(* Logix 5000 project; controller Hardy_1769_Sample_Program vendor 1 type 14 code 151 rev 30.11; software revision 30.02; part 4 of 5 *)
(* tags used below, declared in another part *)
   Control_Bits : BOOL[32];   // Control Bits For All Routines In This Program
   Control_Bits1 : BOOL[32];
   Current_Metric : INT;   // Current Metric Settings
   Default_Return_Flt : HardyFloatWeight;   // Default Return Values With Weight In Foating Point Format
   Default_Return_Int : HardyIntWeight;   // Default Return Values With Weight In Integer Format
   Error_Flag : BOOL;
   Metric : INT;   // New Metric Setting
   Motion : BOOL;
   One_Shot : BOOL[32];   // One Shots For Program Control
   Read_Float_Parameters_0 : HardyFloatParam0;   // Read Parameter 0 Values From Module Using Float Values
   Read_Float_Parameters_1 : HardyFloatParam1;   // Read Parameter 1 Values From Module Using Float Values
   Read_Int_Parameters_0 : HardyIntParam0;   // Read Parameter 0 Values From Module Using Int Values
   Read_Int_Parameters_1 : HardyIntParam1;   // Read Parameter 1 Values From Module Using Int Values
   Sensor_Select : INT;   // Load Cell Selected For Reading Serial Number
   Serial_Number : HardyC2SerialNumber;   // Serial Number of Selected Load Cell Analog With Sensitivity and Capacity
   Signal_Select : INT;   // Signal To Select For Stability Test
   Stability_Float : HardyFloatWeight;   // Results Of Stability Test Float Format
   Stability_Int : HardyIntWeight;   // Results Of Stability Test Int Format
   Status_Return : HardyCmdResult;   // Command Status Returned
   Write_Float_Param_0 : HardyFloatParam0;   // New Parameter 0 Values In Float Format
   Write_Float_Param_1 : HardyFloatParam1;   // New Parameter 1 Values In Float Format
   Write_Int_Param_0 : HardyIntParam0;   // New Parameter 0 Value Int Format
   Write_Int_Param_1 : HardyIntParam1;   // New Parameter 1 Value Int Format
(* Hardy_HI1769_Scale_1, continued *)

ROUTINE Read_Parameters_0   (* ladder *)
// READ PARAMETER 0 VALUES
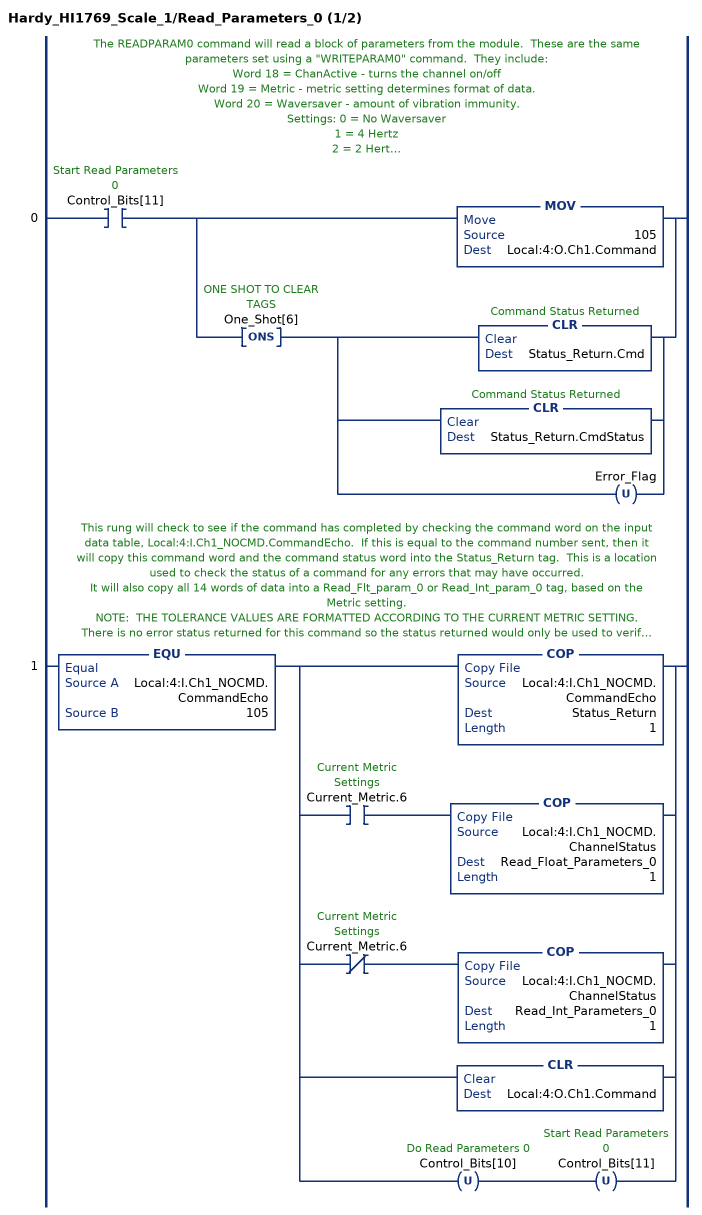
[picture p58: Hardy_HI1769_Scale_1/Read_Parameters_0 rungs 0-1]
   // The READPARAM0 command will read a block of parameters from the module.  These are the same parameters set using a "WRITEPARAM0" command.  They include:
   // Word 18 = ChanActive - turns the channel on/off
   // Word 19 = Metric - metric setting determines format of data.
   // Word 20 = Waversaver - amount of vibration immunity.
   //     Settings: 0 = No Waversaver
   //               1 = 4 Hertz
   //               2 = 2 Hertz
   //               3 = 1 Hertz
   //               4 = 0.5 Hertz
   //               5 = 0.25 Hertz
   // Word 21 = NumAverages - number of readings averaged together
   // Word 22 = ZeroTrackEnable - AutoZero tracking on/off
   // Word 23 = ROC Time Base
   // Word 24 = AutoZeroTolerance, LSW - Auto Zero Tracking tolerance
   // Word 25 = AutoZeroTolerance, MSW - Auto Zero Tracking tolerance
   // Word 26 = Motion Tolerance LSW - used to determine motion
   // Word 27 = Motion Tolerance MSW - used to determine motion
   // Word 28 = Zero Tolerance LSW - tolerance for zero command
   // Word 29 = Zero Tolerance MSW - tolerance for zero command
   // Word 30 = unused
   // Word 31 = unused
   // This rung will initiate the READPARAM0 command by writing the command number, #105, to the output table, LOCAL:4:O.CH1.Command.
   // Here the program will also clear the Status_Return tag and ERROR_FLAG of any previous values before running this command and receiving its return values.
   0: XIC(Control_Bits[11])[MOV(105,Local:4:O.Ch1.Command) ,ONS(One_Shot[6]) [CLR(Status_Return.Cmd) ,CLR(Status_Return.CmdStatus) ,OTU(Error_Flag) ] ];
   // This rung will check to see if the command has completed by checking the command word on the input data table, Local:4:I.Ch1_NOCMD.CommandEcho.  If this is equal to the command number sent, then it will copy this command word and the command status word into the Status_Return tag.  This is a location used to check the status of a command for any errors that may have occurred.
   // It will also copy all 14 words of data into a Read_Flt_param_0 or Read_Int_param_0 tag, based on the Metric setting.
   // NOTE:  THE TOLERANCE VALUES ARE FORMATTED ACCORDING TO THE CURRENT METRIC SETTING.
   // There is no error status returned for this command so the status returned would only be used to verify what command was run last.
   // Finally, the command is cleared from the output table,  Local:4:O.Ch1_NOCMD.Command, and any control bits are cleared.
   1: EQU(Local:4:I.Ch1_NOCMD.CommandEcho,105)[COP(Local:4:I.Ch1_NOCMD.CommandEcho,Status_Return,1) ,XIC(Current_Metric.6) COP(Local:4:I.Ch1_NOCMD.ChannelStatus,Read_Float_Parameters_0,1) ,XIO(Current_Metric.6) COP(Local:4:I.Ch1_NOCMD.ChannelStatus,Read_Int_Parameters_0,1) ,CLR(Local:4:O.Ch1.Command) ,OTU(Control_Bits[10]) OTU(Control_Bits[11]) ];
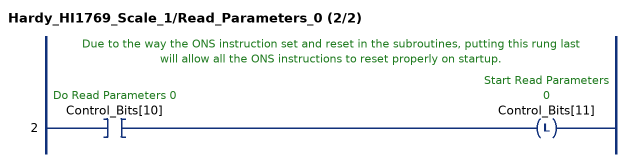
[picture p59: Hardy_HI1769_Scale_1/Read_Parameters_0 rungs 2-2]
   // Due to the way the ONS instruction set and reset in the subroutines, putting this rung last will allow all the ONS instructions to reset properly on startup.
   2: XIC(Control_Bits[10])OTL(Control_Bits[11]);
END_ROUTINE

ROUTINE Read_Parameters_1   (* ladder *)
// READ PARAMETER 1 VALUES
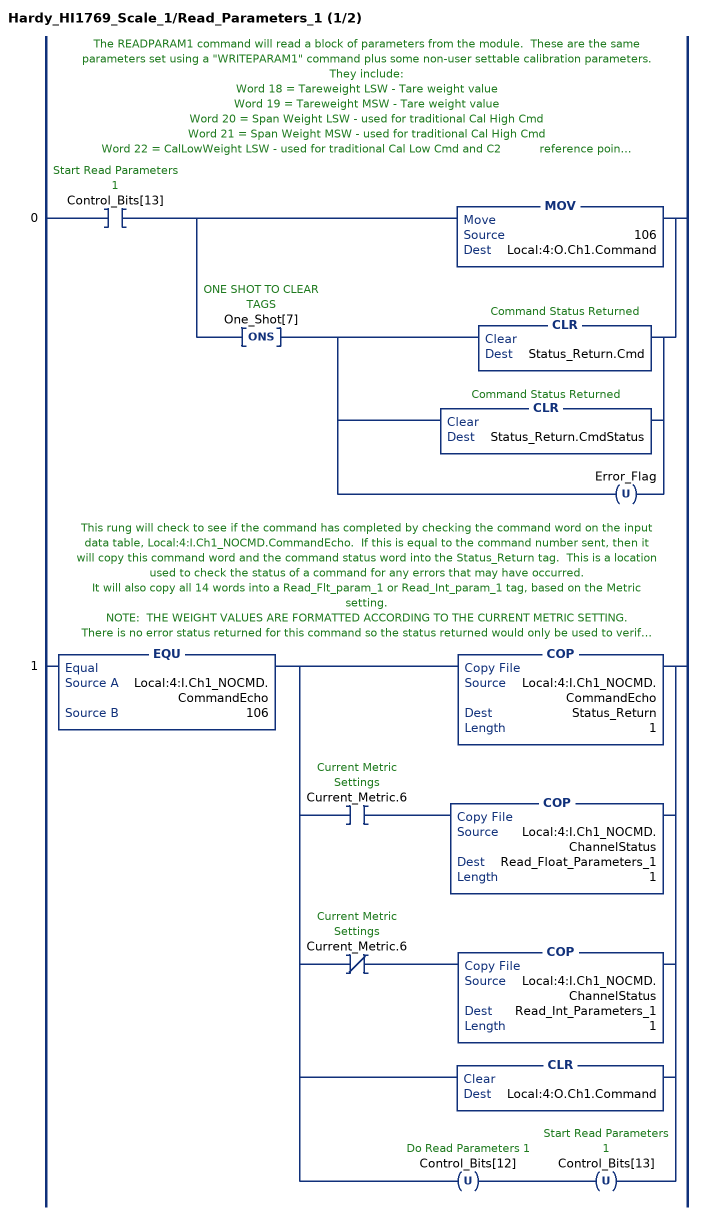
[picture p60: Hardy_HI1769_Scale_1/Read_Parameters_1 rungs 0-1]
   // The READPARAM1 command will read a block of parameters from the module.  These are the same parameters set using a "WRITEPARAM1" command plus some non-user settable calibration parameters.  They include:
   // Word 18 = Tareweight LSW - Tare weight value
   // Word 19 = Tareweight MSW - Tare weight value
   // Word 20 = Span Weight LSW - used for traditional Cal High Cmd
   // Word 21 = Span Weight MSW - used for traditional Cal High Cmd
   // Word 22 = CalLowWeight LSW - used for traditional Cal Low Cmd and C2           reference point
   // Word 23 = CalLowWeight MSW - used for traditional Cal Low Cmd and C2           reference point
   // Word 24 = Zerocount LSW - A/D counts at last ZEROCMD (read only)
   // Word 25 = Zerocount MSW - A/D counts at last ZEROCMD (read only)
   // Word 26 = Calzerocount LSW - A/D counts at zero weight obtained at the last calibration (read only)
   // Word 27 = Calzerocount MSW - A/D counts at zero weight obtained at the last calibration (read only)
   // Word 28 = CalLowCount LSW - A/D counts at CalLowWeight (read only)
   // Word 29 = CalLowCount MSW - A/D counts at CalLowWeight (read only)
   // Word 30 = CalHighCount LSW - A/D counts at span weight (traditional cal only) (read only)
   // Word 31 = CalHighCount MSW - A/D counts at span weight (traditional cal only) (read only)
   // This rung will initiate the READPARAM1 command by writing the command number, #106, to the output table, Local:4:O.Ch1.Command.
   // Here the program will also clear the Status_Return tag and ERROR_FLAG of any previous values before running this command and receiving its return values.
   0: XIC(Control_Bits[13])[MOV(106,Local:4:O.Ch1.Command) ,ONS(One_Shot[7]) [CLR(Status_Return.Cmd) ,CLR(Status_Return.CmdStatus) ,OTU(Error_Flag) ] ];
   // This rung will check to see if the command has completed by checking the command word on the input data table, Local:4:I.Ch1_NOCMD.CommandEcho.  If this is equal to the command number sent, then it will copy this command word and the command status word into the Status_Return tag.  This is a location used to check the status of a command for any errors that may have occurred.
   // It will also copy all 14 words into a Read_Flt_param_1 or Read_Int_param_1 tag, based on the Metric setting.
   // NOTE:  THE WEIGHT VALUES ARE FORMATTED ACCORDING TO THE CURRENT METRIC SETTING.
   // There is no error status returned for this command so the status returned would only be used to verify what command was run last.
   // Finally, the command is cleared from the output table, Local:4:O.Ch1.Command, and any control bits are cleared.
   1: EQU(Local:4:I.Ch1_NOCMD.CommandEcho,106)[COP(Local:4:I.Ch1_NOCMD.CommandEcho,Status_Return,1) ,XIC(Current_Metric.6) COP(Local:4:I.Ch1_NOCMD.ChannelStatus,Read_Float_Parameters_1,1) ,XIO(Current_Metric.6) COP(Local:4:I.Ch1_NOCMD.ChannelStatus,Read_Int_Parameters_1,1) ,CLR(Local:4:O.Ch1.Command) ,OTU(Control_Bits[12]) OTU(Control_Bits[13]) ];
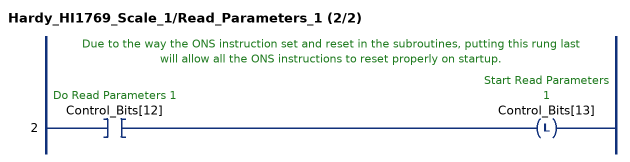
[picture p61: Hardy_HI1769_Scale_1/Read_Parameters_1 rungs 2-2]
   // Due to the way the ONS instruction set and reset in the subroutines, putting this rung last will allow all the ONS instructions to reset properly on startup.
   2: XIC(Control_Bits[12])OTL(Control_Bits[13]);
END_ROUTINE

ROUTINE Read_Serial_Numbers   (* ladder *)
// READS SERIAL NUMBER FROM C2 LOAD CELLS
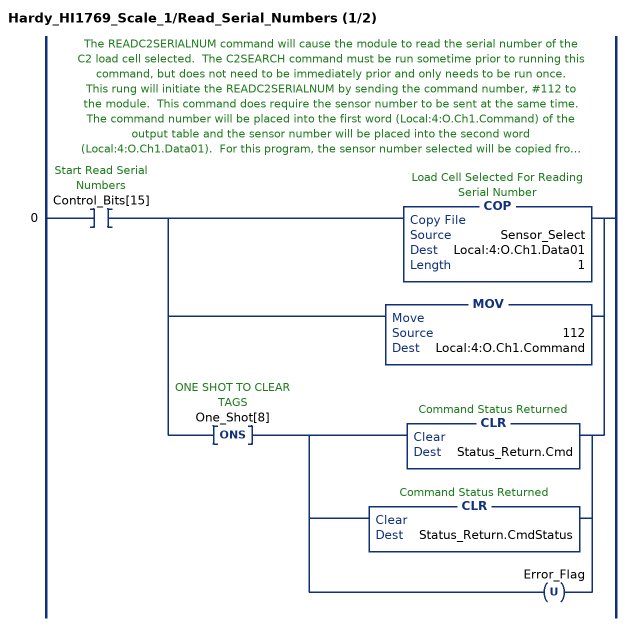
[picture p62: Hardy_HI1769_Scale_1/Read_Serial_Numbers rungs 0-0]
   // The READC2SERIALNUM command will cause the module to read the serial number of the C2 load cell selected.  The C2SEARCH command must be run sometime prior to running this command, but does not need to be immediately prior and only needs to be run once.
   // This rung will initiate the READC2SERIALNUM by sending the command number, #112 to the module.  This command does require the sensor number to be sent at the same time.  The command number will be placed into the first word (Local:4:O.Ch1.Command) of the output table and the sensor number will be placed into the second word (Local:4:O.Ch1.Data01).  For this program, the sensor number selected will be copied from data tag sensor_sel.
   // The data read from the READC2SERIALNUM command contains:
   // word 18 - word 25 = serial number read as ASCII characters
   // word 26 = sensitivity LSW - mv/v rating of load cell
   // word 27 = sensitivity MSW - mv/v rating of load cell
   // word 28 = capacity LSW = capacity of load cell
   // word 29 = capacity MSW = capacity of load cell
   // word 30 = unused
   // word 31 = unused
   // NOTE:  SENSITIVITY IS AN ITEGER WITH 4 DECIMAL PLACES AND CAPACITY IS AN INTEGER WITH ZERO DECIMAL PLACES AND UNITS OF POUNDS.
   // Here the program will also clear the Status_Return tag and ERROR_FLAG of any previous values before running this command and receiving its return values.
   0: XIC(Control_Bits[15])[COP(Sensor_Select,Local:4:O.Ch1.Data01,1) ,MOV(112,Local:4:O.Ch1.Command) ,ONS(One_Shot[8]) [CLR(Status_Return.Cmd) ,CLR(Status_Return.CmdStatus) ,OTU(Error_Flag) ] ];
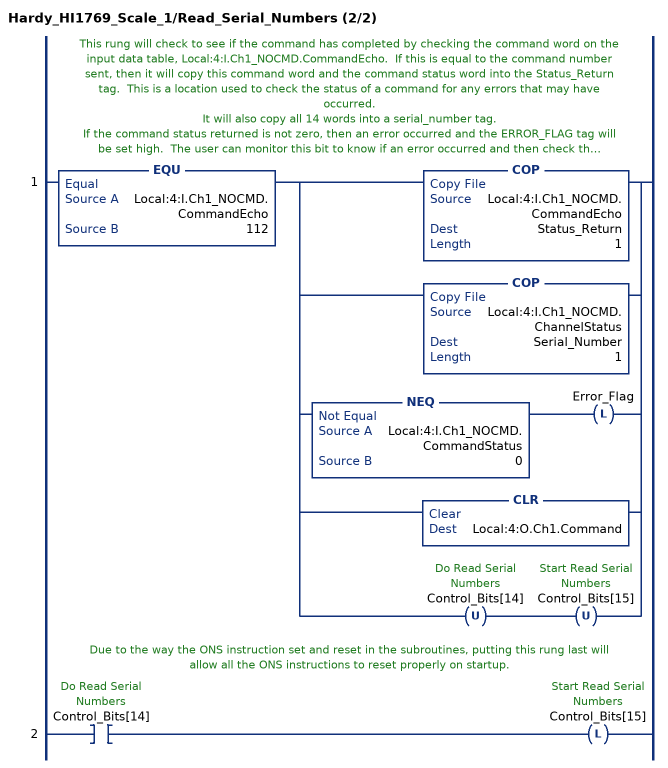
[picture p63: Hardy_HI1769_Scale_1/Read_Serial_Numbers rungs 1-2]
   // This rung will check to see if the command has completed by checking the command word on the input data table, Local:4:I.Ch1_NOCMD.CommandEcho.  If this is equal to the command number sent, then it will copy this command word and the command status word into the Status_Return tag.  This is a location used to check the status of a command for any errors that may have occurred.
   // It will also copy all 14 words into a serial_number tag.
   // If the command status returned is not zero, then an error occurred and the ERROR_FLAG tag will be set high.  The user can monitor this bit to know if an error occurred and then check the Status_Return tag for the command and status return.
   // Finally, the command is cleared from the output table, Local:4:O.Ch1.Command, and any control bits are cleared.
   1: EQU(Local:4:I.Ch1_NOCMD.CommandEcho,112)[COP(Local:4:I.Ch1_NOCMD.CommandEcho,Status_Return,1) ,COP(Local:4:I.Ch1_NOCMD.ChannelStatus,Serial_Number,1) ,NEQ(Local:4:I.Ch1_NOCMD.CommandStatus,0) OTL(Error_Flag) ,CLR(Local:4:O.Ch1.Command) ,OTU(Control_Bits[14]) OTU(Control_Bits[15]) ];
   // Due to the way the ONS instruction set and reset in the subroutines, putting this rung last will allow all the ONS instructions to reset properly on startup.
   2: XIC(Control_Bits[14])OTL(Control_Bits[15]);
END_ROUTINE

ROUTINE Reload_Non_Volatile   (* ladder *)
// RESTORE SETTINGS FROM NON-VOLATILE MEMORY
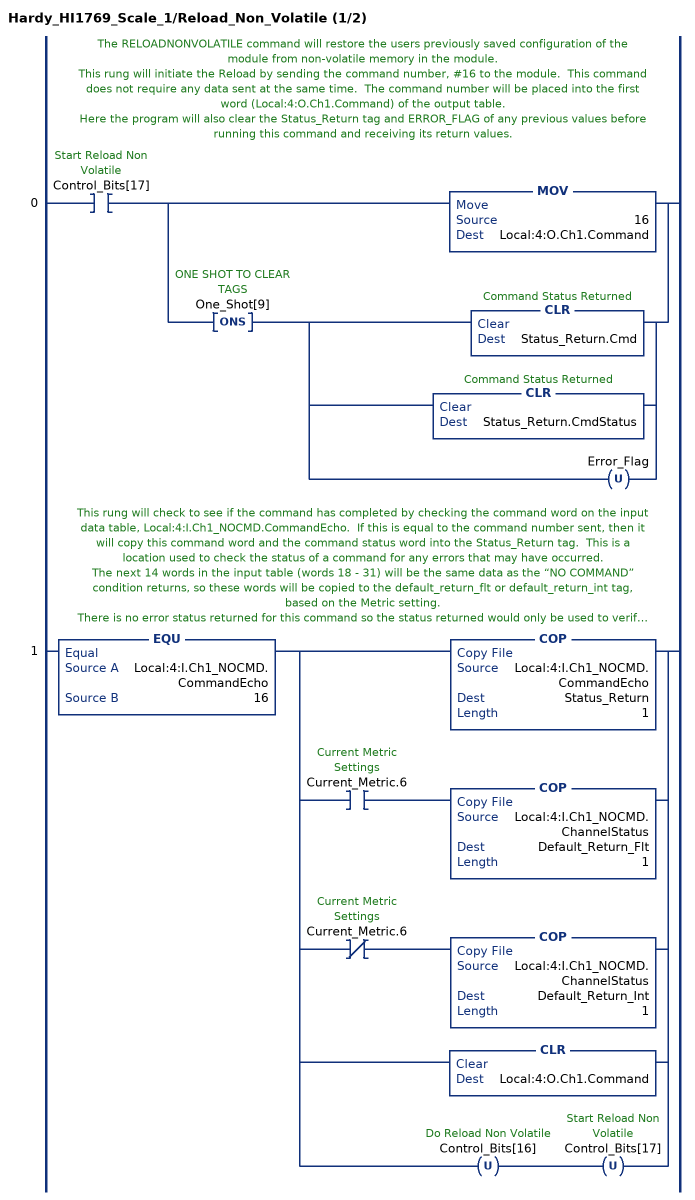
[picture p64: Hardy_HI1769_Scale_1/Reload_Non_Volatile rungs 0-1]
   // The RELOADNONVOLATILE command will restore the users previously saved configuration of the module from non-volatile memory in the module.
   // This rung will initiate the Reload by sending the command number, #16 to the module.  This command does not require any data sent at the same time.  The command number will be placed into the first word (Local:4:O.Ch1.Command) of the output table.
   // Here the program will also clear the Status_Return tag and ERROR_FLAG of any previous values before running this command and receiving its return values.
   0: XIC(Control_Bits[17])[MOV(16,Local:4:O.Ch1.Command) ,ONS(One_Shot[9]) [CLR(Status_Return.Cmd) ,CLR(Status_Return.CmdStatus) ,OTU(Error_Flag) ] ];
   // This rung will check to see if the command has completed by checking the command word on the input data table, Local:4:I.Ch1_NOCMD.CommandEcho.  If this is equal to the command number sent, then it will copy this command word and the command status word into the Status_Return tag.  This is a location used to check the status of a command for any errors that may have occurred.
   // The next 14 words in the input table (words 18 - 31) will be the same data as the “NO COMMAND” condition returns, so these words will be copied to the default_return_flt or default_return_int tag, based on the Metric setting.
   // There is no error status returned for this command so the status returned would only be used to verify what command was run last.
   // Finally, the command is cleared from the output table, Local:4:O.Ch1.Command, and any control bits are cleared.
   1: EQU(Local:4:I.Ch1_NOCMD.CommandEcho,16)[COP(Local:4:I.Ch1_NOCMD.CommandEcho,Status_Return,1) ,XIC(Current_Metric.6) COP(Local:4:I.Ch1_NOCMD.ChannelStatus,Default_Return_Flt,1) ,XIO(Current_Metric.6) COP(Local:4:I.Ch1_NOCMD.ChannelStatus,Default_Return_Int,1) ,CLR(Local:4:O.Ch1.Command) ,OTU(Control_Bits[16]) OTU(Control_Bits[17]) ];
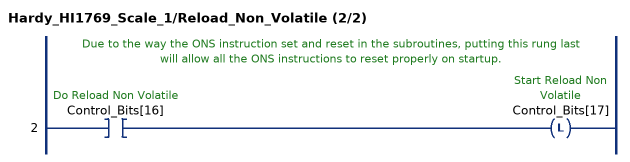
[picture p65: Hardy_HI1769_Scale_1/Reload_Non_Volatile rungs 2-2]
   // Due to the way the ONS instruction set and reset in the subroutines, putting this rung last will allow all the ONS instructions to reset properly on startup.
   2: XIC(Control_Bits[16])OTL(Control_Bits[17]);
END_ROUTINE

ROUTINE Stability_Test   (* ladder *)
// ALLOWS CHECK OF STABILITY OF SYSTEM
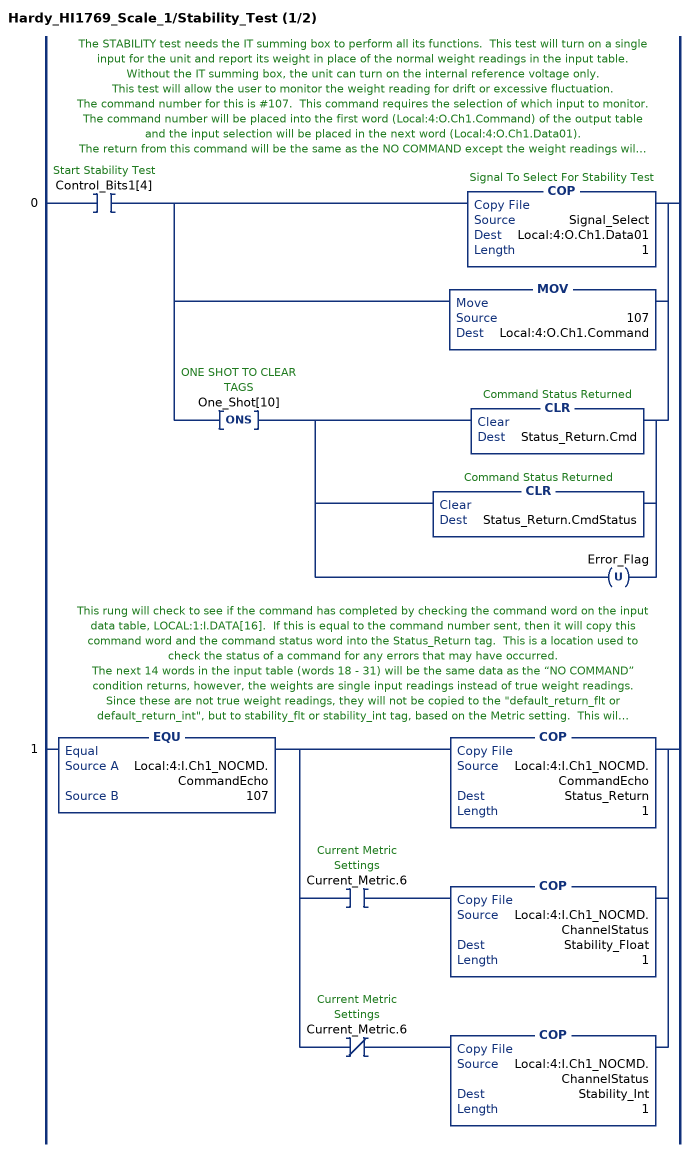
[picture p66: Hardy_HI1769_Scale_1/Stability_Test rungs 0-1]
   // The STABILITY test needs the IT summing box to perform all its functions.  This test will turn on a single input for the unit and report its weight in place of the normal weight readings in the input table.  Without the IT summing box, the unit can turn on the internal reference voltage only.
   // This test will allow the user to monitor the weight reading for drift or excessive fluctuation.
   // The command number for this is #107.  This command requires the selection of which input to monitor.  The command number will be placed into the first word (Local:4:O.Ch1.Command) of the output table and the input selection will be placed in the next word (Local:4:O.Ch1.Data01).
   // The return from this command will be the same as the NO COMMAND except the weight readings will reflect the reading based only on the input selected.  The selections are:
   // 0 = Internal reference voltage - checks if the input circuits are stable
   // 1-4 = load cell selection - checks if selected l/c is stable
   // 5 = reference voltage from IT JBOX - checks if cable is causing noise
   // All weight values will then be affected by this selection during the time the command number is left unchanged in the output table.
   // This rung will copy the selection into the output table at Local:4:O.Ch1.Data01 (from signal_select), and the command number for the STABILITY test, command #107, into word Local:4:O.Ch1.Command.  The user must have the selection value entered into the signal_select tag prior to running this routine, otherwise an error could occur.
   // Here the program will also clear the Status_Return tag and ERROR_FLAG of any previous values before running this command and receiving its return values.
   0: XIC(Control_Bits1[4])[COP(Signal_Select,Local:4:O.Ch1.Data01,1) ,MOV(107,Local:4:O.Ch1.Command) ,ONS(One_Shot[10]) [CLR(Status_Return.Cmd) ,CLR(Status_Return.CmdStatus) ,OTU(Error_Flag) ] ];
   // This rung will check to see if the command has completed by checking the command word on the input data table, LOCAL:1:I.DATA[16].  If this is equal to the command number sent, then it will copy this command word and the command status word into the Status_Return tag.  This is a location used to check the status of a command for any errors that may have occurred.
   // The next 14 words in the input table (words 18 - 31) will be the same data as the “NO COMMAND” condition returns, however, the weights are single input readings instead of true weight readings.  Since these are not true weight readings, they will not be copied to the "default_return_flt or default_return_int", but to stability_flt or stability_int tag, based on the Metric setting.  This will continue until the "STOP STABILITY" bit is trigger by the user.
   // If the command status returned is not zero, then an error occurred and the ERROR_FLAG tag will be set high.  The user can monitor this bit to know if an error occurred and then check the Status_Return tag for the command and status return.
   // This rung will check to see if the command has completed by checking the command word on the input data table, Local:4:I.Ch1_NOCMD.CommandEcho.  If this is equal to the command number sent, then it will copy this command word and the command status word into the Status_Return tag.  This is a location used to check the status of a command for any errors that may have occurred.
   // The next 14 words in the input table (words 18 - 31) will be the same data as the “NO COMMAND” condition returns, however, the weights are single input readings instead of true weight readings.  Since these are not true weight readings, they will not be copied to the "default_return_flt or default_return_int", but to stability_flt or stability_int tag, based on the Metric setting.  This will continue until the "STOP STABILITY" bit is trigger by the user.
   // If the command status returned is not zero, then an error occurred and the ERROR_FLAG tag will be set high.  The user can monitor this bit to know if an error occurred and then check the Status_Return tag for the command and status return.
   1: EQU(Local:4:I.Ch1_NOCMD.CommandEcho,107)[COP(Local:4:I.Ch1_NOCMD.CommandEcho,Status_Return,1) ,XIC(Current_Metric.6) COP(Local:4:I.Ch1_NOCMD.ChannelStatus,Stability_Float,1) ,XIO(Current_Metric.6) COP(Local:4:I.Ch1_NOCMD.ChannelStatus,Stability_Int,1) ];
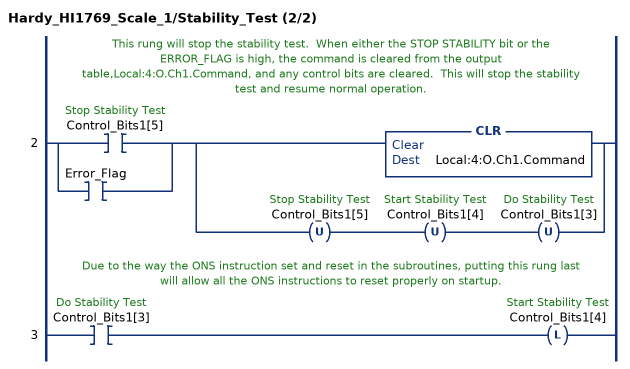
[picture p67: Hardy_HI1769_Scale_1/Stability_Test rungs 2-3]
   // This rung will stop the stability test.  When either the STOP STABILITY bit or the ERROR_FLAG is high, the command is cleared from the output table,Local:4:O.Ch1.Command, and any control bits are cleared.  This will stop the stability test and resume normal operation.
   2: [XIC(Control_Bits1[5]) ,XIC(Error_Flag) ][CLR(Local:4:O.Ch1.Command) ,OTU(Control_Bits1[5]) OTU(Control_Bits1[4]) OTU(Control_Bits1[3]) ];
   // Due to the way the ONS instruction set and reset in the subroutines, putting this rung last will allow all the ONS instructions to reset properly on startup.
   3: XIC(Control_Bits1[3])OTL(Control_Bits1[4]);
END_ROUTINE

ROUTINE Tare   (* ladder *)
// TARE THE CURRENT NET WEIGHT
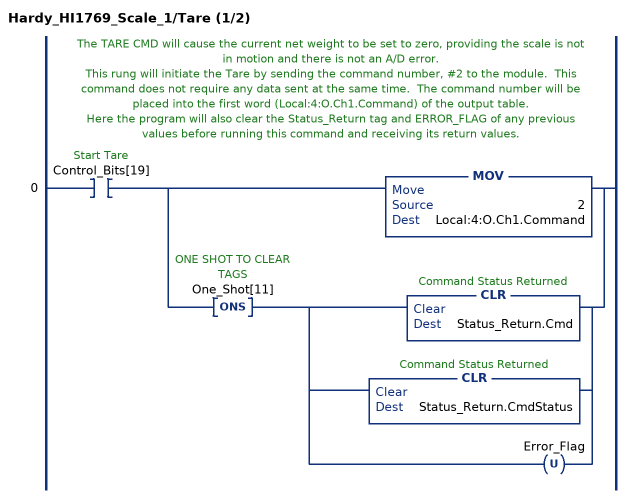
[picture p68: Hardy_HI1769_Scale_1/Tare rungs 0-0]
   // The TARE CMD will cause the current net weight to be set to zero, providing the scale is not in motion and there is not an A/D error.
   // This rung will initiate the Tare by sending the command number, #2 to the module.  This command does not require any data sent at the same time.  The command number will be placed into the first word (Local:4:O.Ch1.Command) of the output table.
   // Here the program will also clear the Status_Return tag and ERROR_FLAG of any previous values before running this command and receiving its return values.
   0: XIC(Control_Bits[19])[MOV(2,Local:4:O.Ch1.Command) ,ONS(One_Shot[11]) [CLR(Status_Return.Cmd) ,CLR(Status_Return.CmdStatus) ,OTU(Error_Flag) ] ];
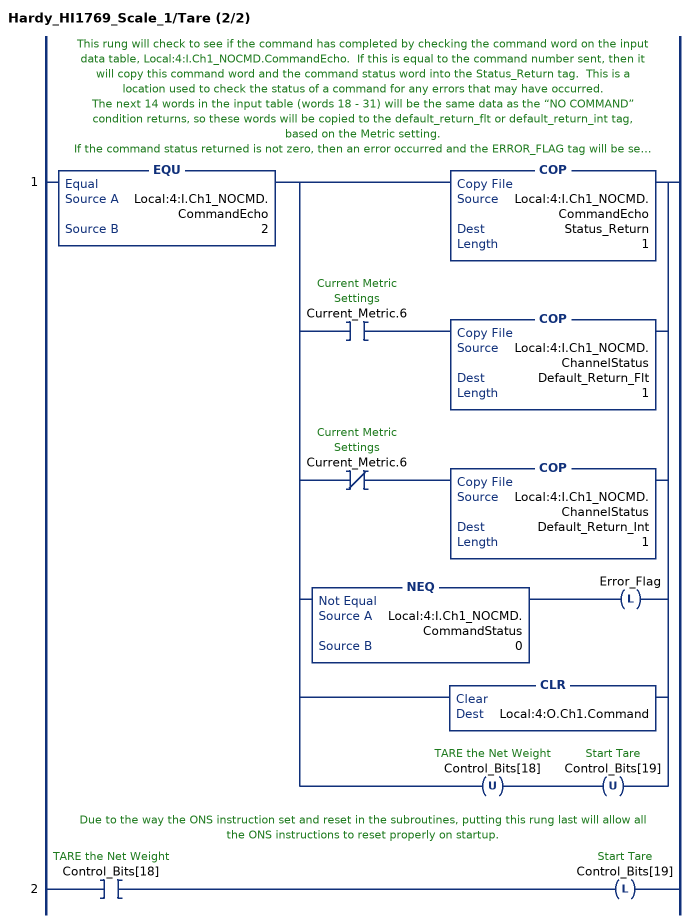
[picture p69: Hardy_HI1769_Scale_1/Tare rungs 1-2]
   // This rung will check to see if the command has completed by checking the command word on the input data table, Local:4:I.Ch1_NOCMD.CommandEcho.  If this is equal to the command number sent, then it will copy this command word and the command status word into the Status_Return tag.  This is a location used to check the status of a command for any errors that may have occurred.
   // The next 14 words in the input table (words 18 - 31) will be the same data as the “NO COMMAND” condition returns, so these words will be copied to the default_return_flt or default_return_int tag, based on the Metric setting.
   // If the command status returned is not zero, then an error occurred and the ERROR_FLAG tag will be set high.  The user can monitor this bit to know if an error occurred and then check the Status_Return tag for the command and status return.
   // Finally, the command is cleared from the output table, Local:4:O.Ch1.Command, and any control bits are cleared.
   1: EQU(Local:4:I.Ch1_NOCMD.CommandEcho,2)[COP(Local:4:I.Ch1_NOCMD.CommandEcho,Status_Return,1) ,XIC(Current_Metric.6) COP(Local:4:I.Ch1_NOCMD.ChannelStatus,Default_Return_Flt,1) ,XIO(Current_Metric.6) COP(Local:4:I.Ch1_NOCMD.ChannelStatus,Default_Return_Int,1) ,NEQ(Local:4:I.Ch1_NOCMD.CommandStatus,0) OTL(Error_Flag) ,CLR(Local:4:O.Ch1.Command) ,OTU(Control_Bits[18]) OTU(Control_Bits[19]) ];
   // Due to the way the ONS instruction set and reset in the subroutines, putting this rung last will allow all the ONS instructions to reset properly on startup.
   2: XIC(Control_Bits[18])OTL(Control_Bits[19]);
END_ROUTINE

ROUTINE Write_Metric   (* ladder *)
// WRITE NET METRIC SETTING TO THE MODULE
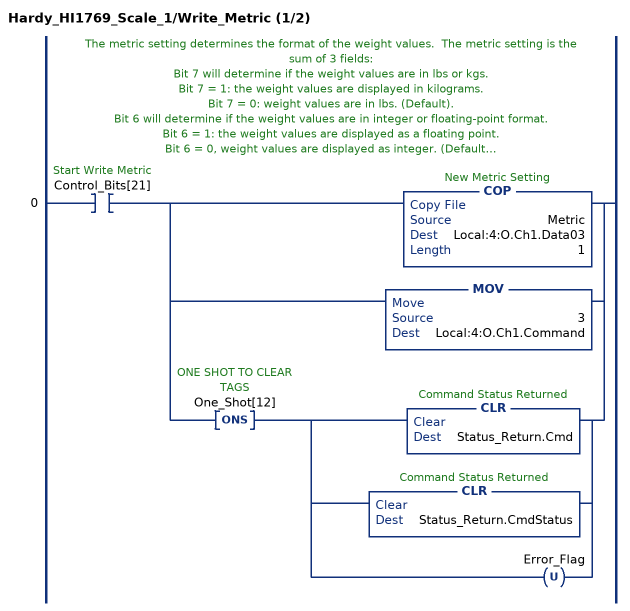
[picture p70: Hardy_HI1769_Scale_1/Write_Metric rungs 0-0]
   // The metric setting determines the format of the weight values.  The metric setting is the sum of 3 fields:
   // Bit 7 will determine if the weight values are in lbs or kgs.
   // Bit 7 = 1: the weight values are displayed in kilograms.
   //   Bit 7 = 0: weight values are in lbs. (Default).
   // Bit 6 will determine if the weight values are in integer or floating-point format.
   // Bit 6 = 1: the weight values are displayed as a floating point.
   // Bit 6 = 0, weight values are displayed as integer. (Default)
   // Bits 0, 1, & 2 – this is a binary value to determine the number of decimal places transferred.  This only applies if bit 6 = 0.
   // This routine will write a new metric setting to the module.  This involves sending the WRITEMETRIC command number and the new metric value.  The command number for this is #3.  This command requires the new metric value at the same time.  The command number will be placed into the first word (Local:4:O.Ch1.Command) of the output table and the new metric value will be placed in the forth word (Local:4:O.Ch1.Data03).  All weight values will then be affected by this new metric setting, including values being written after this takes effect.
   // The weight values affected by the metric setting are:
   // Weight readings, both Gross and Net read during a “NO COMMAND” condition and during other routines returning these values;
   // The AutoZero Tolerance, Motion Tolerance, and Zero Tolerance in both the WRITE_PARAMETER_0 and READ_PARAMETER_0 routines;
   // Tare weight, Span weight, and CalLow weight in both the WRITE_PARAMETER_1 and READ_PARAMETER_1 routines.
   // Weight values read during the INTEGRATED_TECHNICIAN routine.
   // This rung will copy the new metric value into the output table at word Local:4:O.Ch1.Data03 (from Metric tag), and the command number for setting a new metric setting, command #3, into word Local:4:O.Ch1.Command of the output table.  The user must have the new value entered into the Metric tag prior to running this routine, otherwise unexpected results could occur.
   // Here the program will also clear the Status_Return tag and ERROR_FLAG of any previous values before running this command and receiving its return values.
   0: XIC(Control_Bits[21])[COP(Metric,Local:4:O.Ch1.Data03,1) ,MOV(3,Local:4:O.Ch1.Command) ,ONS(One_Shot[12]) [CLR(Status_Return.Cmd) ,CLR(Status_Return.CmdStatus) ,OTU(Error_Flag) ] ];
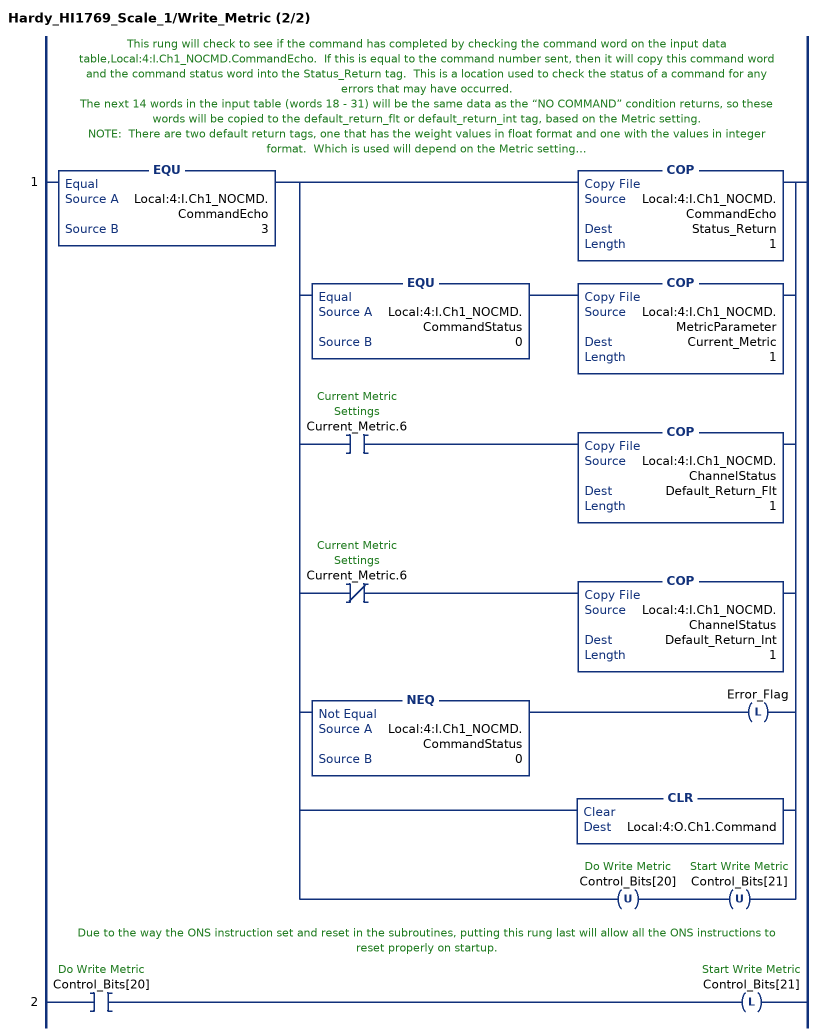
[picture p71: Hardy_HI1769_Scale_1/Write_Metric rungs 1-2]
   // This rung will check to see if the command has completed by checking the command word on the input data table,Local:4:I.Ch1_NOCMD.CommandEcho.  If this is equal to the command number sent, then it will copy this command word and the command status word into the Status_Return tag.  This is a location used to check the status of a command for any errors that may have occurred.
   // The next 14 words in the input table (words 18 - 31) will be the same data as the “NO COMMAND” condition returns, so these words will be copied to the default_return_flt or default_return_int tag, based on the Metric setting.
   // NOTE:  There are two default return tags, one that has the weight values in float format and one with the values in integer format.  Which is used will depend on the Metric setting.
   // If the command status returned is not zero, then an error occurred and the ERROR_FLAG tag will be set high.  The user can monitor this bit to know if an error occurred and then check the Status_Return tag for the command and status return.
   // If the command status return is a value of 3, then the command failed because the new metric setting is not a valid value.
   // Finally, the command is cleared from the output table, Local:4:O.Ch1.Command, and any control bits are cleared.
   1: EQU(Local:4:I.Ch1_NOCMD.CommandEcho,3)[COP(Local:4:I.Ch1_NOCMD.CommandEcho,Status_Return,1) ,EQU(Local:4:I.Ch1_NOCMD.CommandStatus,0) COP(Local:4:I.Ch1_NOCMD.MetricParameter,Current_Metric,1) ,XIC(Current_Metric.6) COP(Local:4:I.Ch1_NOCMD.ChannelStatus,Default_Return_Flt,1) ,XIO(Current_Metric.6) COP(Local:4:I.Ch1_NOCMD.ChannelStatus,Default_Return_Int,1) ,NEQ(Local:4:I.Ch1_NOCMD.CommandStatus,0) OTL(Error_Flag) ,CLR(Local:4:O.Ch1.Command) ,OTU(Control_Bits[20]) OTU(Control_Bits[21]) ];
   // Due to the way the ONS instruction set and reset in the subroutines, putting this rung last will allow all the ONS instructions to reset properly on startup.
   2: XIC(Control_Bits[20])OTL(Control_Bits[21]);
END_ROUTINE

ROUTINE Write_Parameters_0   (* ladder *)
// WRITES NEW PARAMETER 0 VALUES
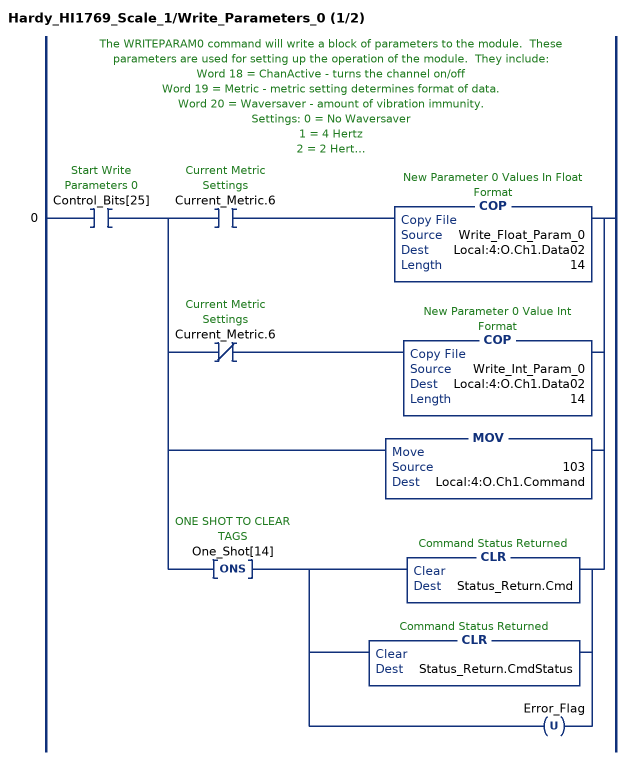
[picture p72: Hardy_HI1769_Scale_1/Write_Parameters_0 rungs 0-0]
   // The WRITEPARAM0 command will write a block of parameters to the module.  These parameters are used for setting up the operation of the module.  They include:
   // Word 18 = ChanActive - turns the channel on/off
   // Word 19 = Metric - metric setting determines format of data.
   // Word 20 = Waversaver - amount of vibration immunity.
   //     Settings: 0 = No Waversaver
   //               1 = 4 Hertz
   //               2 = 2 Hertz
   //               3 = 1 Hertz
   //               4 = 0.5 Hertz
   //               5 = 0.25 Hertz
   // Word 21 = NumAverages - number of readings averaged together
   // Word 22 = ZeroTrackEnable - AutoZero tracking on/off
   // Word 23 = ROC Time Base
   // Word 24 = AutoZeroTolerance, LSW - Auto Zero Tracking tolerance
   // Word 25 = AutoZeroTolerance, MSW - Auto Zero Tracking tolerance
   // Word 26 = Motion Tolerance LSW - used to determine motion
   // Word 27 = Motion Tolerance MSW - used to determine motion
   // Word 28 = Zero Tolerance LSW - tolerance for zero command
   // Word 29 = Zero Tolerance MSW - tolerance for zero command
   // Word 30 = unused
   // Word 31 = unused
   // NOTE:  THE TOLERANCE VALUES ARE FORMATTED ACCORDING TO THE CURRENT METRIC SETTING.  IF THE METRIC SETTING IS SET FOR FLOATING POINT FORMAT, THESE VALUES MUST BE WRITTEN IN THE FLOATING POINT FORMAT TO BE VALID.
   // These parameters must be entered into the output table prior to entering the command number.
   // This rung will copy 16 words containing the command number, #103, and the above words to the output table, Local:4:O.Ch1.Command through LOCAL:4:O.DATA15.  This program is using the “write_flt_param_0” or “write_int_param_0” data tag, based on the Metric setting, to copy the data from.  All the parameter data must be valid to prevent an error.  If an error occurs, the Command Status return will contain the offset location indicating which parameter was in error.
   // NOTE:  You cannot write a single parameter.  All parameters will be written at the same time.
   // To write a single parameter, first do a READPARAM0 command, copy the parameters read to the output, change the parameter value you need to change, then set the command word to initiate the write.
   // NOTE:  THE METRIC PARAMETER IS APPLIED LAST, WHICH MEANS THAT ALL PARAMETERS ARE INTERPRETED ACCORDING TO THE CURRENT METRIC VALUE AT THE TIME OF THE WRITE.  THIS ALSO MEANS THAT THE PARAMETERS TAG USED WILL BE BASED ON THE CURRENT METRIC SETTING, SO BE SURE TO USE THE TAG THAT WILL BE WRITTEN.  EXAMPLE:  IF THE CURRENT METRIC SETTING IS INTEGER, AND YOU ARE GOING TO CHANGE IT TO FLOAT, YOUR WRITE PARAMETERS WILL USE THE INTEGER TAG, NOT THE FLOAT TAG FOR THE WRITE.  IF YOU CHANGE THE METRIC SETTING IN THE INTEGER TAG AND WRITE IT, THE NEXT WRITE WILL USE THE FLOAT TAG SINCE THE METRIC SETTING WAS CHANGED.
   // Here the program will also clear the Status_Return tag and ERROR_FLAG of any previous values before running this command and receiving its return values.
   0: XIC(Control_Bits[25])[XIC(Current_Metric.6) COP(Write_Float_Param_0,Local:4:O.Ch1.Data02,14) ,XIO(Current_Metric.6) COP(Write_Int_Param_0,Local:4:O.Ch1.Data02,14) ,MOV(103,Local:4:O.Ch1.Command) ,ONS(One_Shot[14]) [CLR(Status_Return.Cmd) ,CLR(Status_Return.CmdStatus) ,OTU(Error_Flag) ] ];
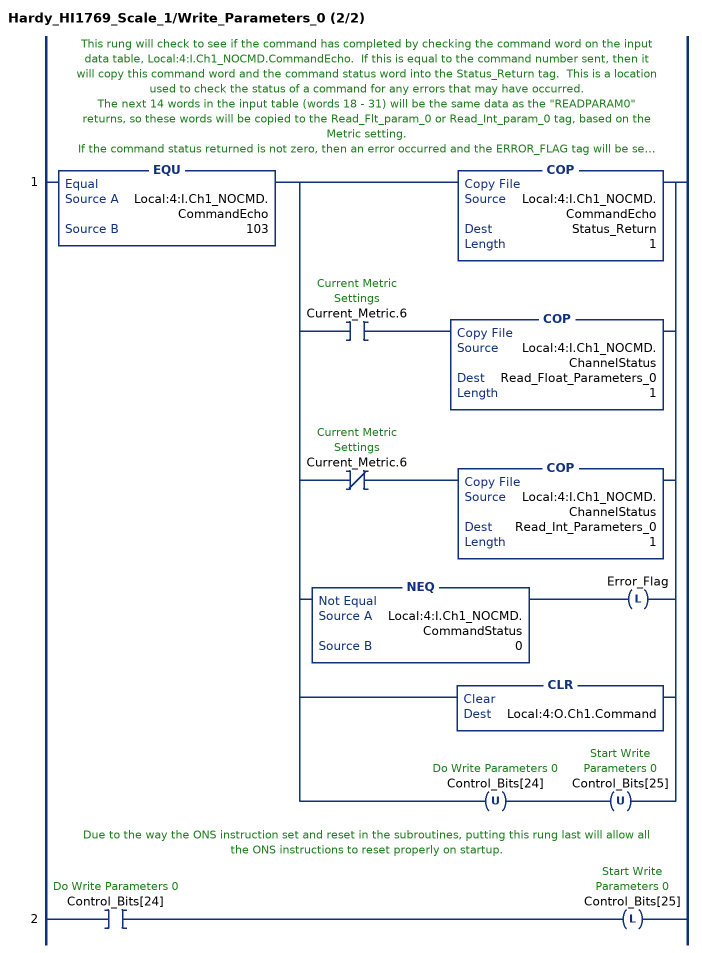
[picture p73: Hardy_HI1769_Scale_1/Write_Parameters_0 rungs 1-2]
   // This rung will check to see if the command has completed by checking the command word on the input data table, Local:4:I.Ch1_NOCMD.CommandEcho.  If this is equal to the command number sent, then it will copy this command word and the command status word into the Status_Return tag.  This is a location used to check the status of a command for any errors that may have occurred.
   // The next 14 words in the input table (words 18 - 31) will be the same data as the "READPARAM0" returns, so these words will be copied to the Read_Flt_param_0 or Read_Int_param_0 tag, based on the Metric setting.
   // If the command status returned is not zero, then an error occurred and the ERROR_FLAG tag will be set high.  The user can monitor this bit to know if an error occurred and then check the Status_Return tag for the command and status return.  The status returned, if not zero, will be an indication of which word location is invalid.
   // Finally, the command is cleared from the output table, Local:4:O.Ch1.Command, and any control bits are cleared.
   1: EQU(Local:4:I.Ch1_NOCMD.CommandEcho,103)[COP(Local:4:I.Ch1_NOCMD.CommandEcho,Status_Return,1) ,XIC(Current_Metric.6) COP(Local:4:I.Ch1_NOCMD.ChannelStatus,Read_Float_Parameters_0,1) ,XIO(Current_Metric.6) COP(Local:4:I.Ch1_NOCMD.ChannelStatus,Read_Int_Parameters_0,1) ,NEQ(Local:4:I.Ch1_NOCMD.CommandStatus,0) OTL(Error_Flag) ,CLR(Local:4:O.Ch1.Command) ,OTU(Control_Bits[24]) OTU(Control_Bits[25]) ];
   // Due to the way the ONS instruction set and reset in the subroutines, putting this rung last will allow all the ONS instructions to reset properly on startup.
   2: XIC(Control_Bits[24])OTL(Control_Bits[25]);
END_ROUTINE

ROUTINE Write_Parameters_1   (* ladder *)
// WRITE PARAMETER 1 VALUES TO MODULE
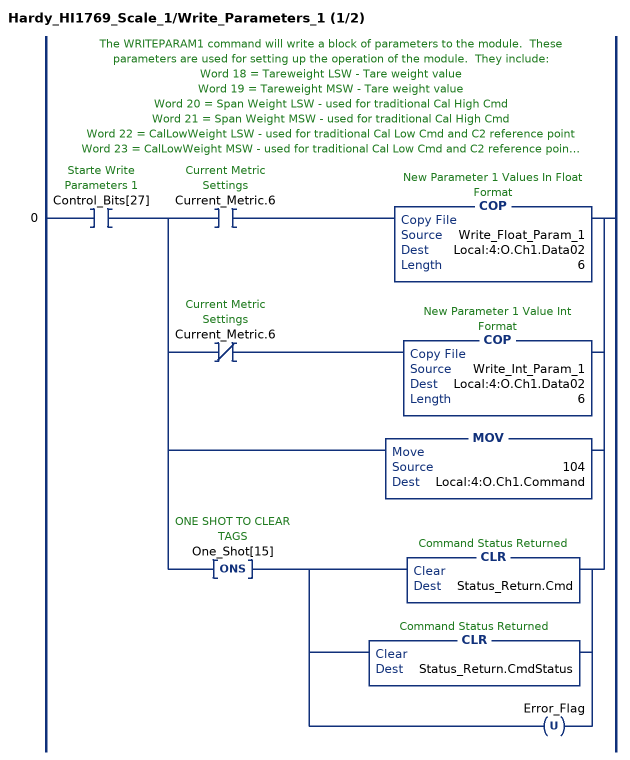
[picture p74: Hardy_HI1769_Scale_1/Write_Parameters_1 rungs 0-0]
   // The WRITEPARAM1 command will write a block of parameters to the module.  These parameters are used for setting up the operation of the module.  They include:
   // Word 18 = Tareweight LSW - Tare weight value
   // Word 19 = Tareweight MSW - Tare weight value
   // Word 20 = Span Weight LSW - used for traditional Cal High Cmd
   // Word 21 = Span Weight MSW - used for traditional Cal High Cmd
   // Word 22 = CalLowWeight LSW - used for traditional Cal Low Cmd and C2 reference point
   // Word 23 = CalLowWeight MSW - used for traditional Cal Low Cmd and C2 reference point
   // Word 24 = unused
   // Word 25 = unused
   // Word 26 = unused
   // Word 27 = unused
   // Word 28 = unused
   // Word 29 = unused
   // Word 30 = unused
   // Word 31 = unused
   // NOTE:  THESE VALUES ARE FORMATTED ACCORDING TO THE CURRENT METRIC SETTING.  IF THE METRIC SETTING IS SET FOR FLOATING POINT FORMAT, THESE VALUES MUST BE WRITTEN IN THE FLOATING POINT FORMAT TO BE VALID.
   // These parameters must be entered into the output table prior to entering the command number.
   // This rung will copy 6 words containing the parameter values to the output table, Local:4:O.Ch1.Data02, and the
   // command number, #104, to the output table, Local:4:O.Ch1.Command.  This program is using write_flt_param_0 or write_int_param_0, based on the Metric setting, to copy the data from.  All the parameter data must be valid to prevent an error.  If an error occurs, the Command Status return will contain the offset location indicating which parameter was in error.
   // NOTE:  You cannot write a single parameter.  All parameters will be written at the same time.
   // To write a single parameter, first do a READPARAM1 command, copy the parameters read to the output, change the parameter value you need to change, then set the command word to initiate the write.
   // Here the program will also clear the Status_Return tag and ERROR_FLAG of any previous values before running this command and receiving its return values.
   0: XIC(Control_Bits[27])[XIC(Current_Metric.6) COP(Write_Float_Param_1,Local:4:O.Ch1.Data02,6) ,XIO(Current_Metric.6) COP(Write_Int_Param_1,Local:4:O.Ch1.Data02,6) ,MOV(104,Local:4:O.Ch1.Command) ,ONS(One_Shot[15]) [CLR(Status_Return.Cmd) ,CLR(Status_Return.CmdStatus) ,OTU(Error_Flag) ] ];
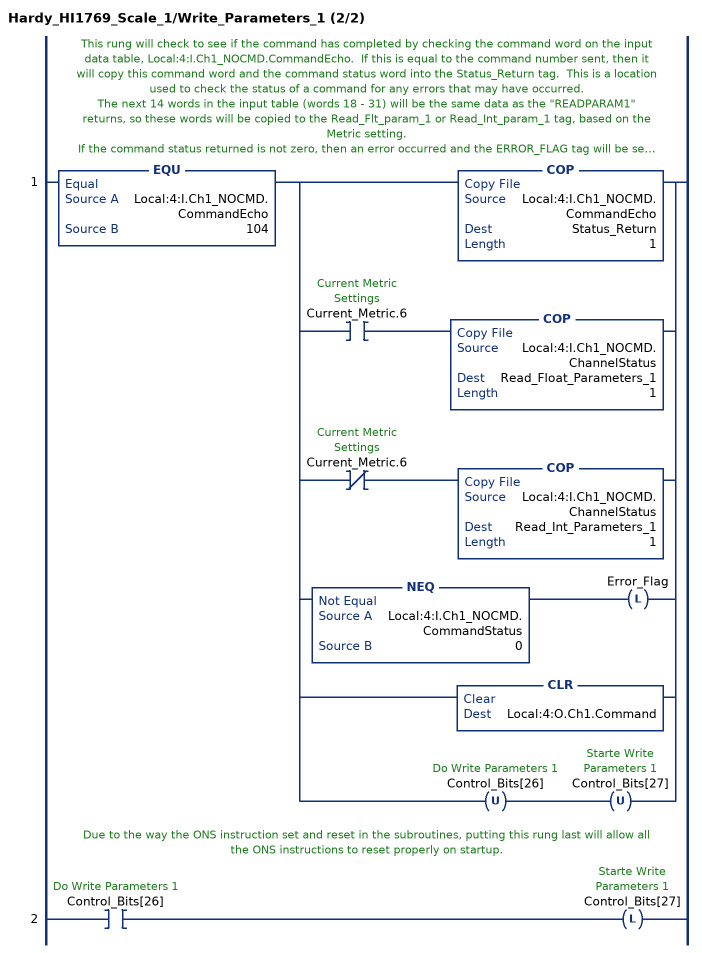
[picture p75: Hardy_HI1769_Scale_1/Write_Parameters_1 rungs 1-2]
   // This rung will check to see if the command has completed by checking the command word on the input data table, Local:4:I.Ch1_NOCMD.CommandEcho.  If this is equal to the command number sent, then it will copy this command word and the command status word into the Status_Return tag.  This is a location used to check the status of a command for any errors that may have occurred.
   // The next 14 words in the input table (words 18 - 31) will be the same data as the "READPARAM1" returns, so these words will be copied to the Read_Flt_param_1 or Read_Int_param_1 tag, based on the Metric setting.
   // If the command status returned is not zero, then an error occurred and the ERROR_FLAG tag will be set high.  The user can monitor this bit to know if an error occurred and then check the Status_Return tag for the command and status return.  The status returned, if not zero, will be an indication of which word location is invalid.
   // Finally, the command is cleared from the output table, Local:4:O.Ch1.Command, and any control bits are cleared.
   1: EQU(Local:4:I.Ch1_NOCMD.CommandEcho,104)[COP(Local:4:I.Ch1_NOCMD.CommandEcho,Status_Return,1) ,XIC(Current_Metric.6) COP(Local:4:I.Ch1_NOCMD.ChannelStatus,Read_Float_Parameters_1,1) ,XIO(Current_Metric.6) COP(Local:4:I.Ch1_NOCMD.ChannelStatus,Read_Int_Parameters_1,1) ,NEQ(Local:4:I.Ch1_NOCMD.CommandStatus,0) OTL(Error_Flag) ,CLR(Local:4:O.Ch1.Command) ,OTU(Control_Bits[26]) OTU(Control_Bits[27]) ];
   // Due to the way the ONS instruction set and reset in the subroutines, putting this rung last will allow all the ONS instructions to reset properly on startup.
   2: XIC(Control_Bits[26])OTL(Control_Bits[27]);
END_ROUTINE
